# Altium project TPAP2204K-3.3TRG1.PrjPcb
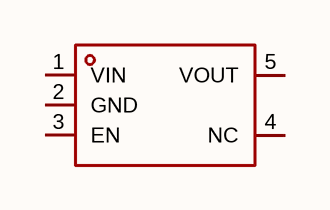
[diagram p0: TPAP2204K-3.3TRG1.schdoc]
1 sheet, 1 parts. Net scope: global (net labels, ports and power ports of the same name join across sheets).

## Sheet TPAP2204K-3.3TRG1.schdoc
size 127 x 101 mm

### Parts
U?  tpap2204k-3.3trg1  [SOT-23-5_L2.9-W1.6-P0.95-LS2.8-BL]  (value not drawn)

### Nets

Not connected (* = marked no-connect by the designer): U? 1(VIN) 2(GND) 3(EN) 4(NC) 5(VOUT)

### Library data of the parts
U? = tpap2204k-3.3trg1: 输出极性:正极;工作电压:36V;输出电压:3.3V;输出电流:200mA;电源纹波抑制比(PSRR):70dB@(100Hz);输出类型:固定;; Manufacturer: TECH PUBLIC(台舟); AddInBom: yes; ModelId: 018c57e721114987ae90467fe9f1d259; ModelTransform: 114.96,110.236,0,0,0,0,0,0,0; Output Configuration: 正极; Voltage - Supply: 36V; Output Voltage: 3.3V; Output Current: 200mA; Voltage Dropout: 750mV@(100mA); standby current: 2uA; Output Type: 固定; Number of Outputs: 1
